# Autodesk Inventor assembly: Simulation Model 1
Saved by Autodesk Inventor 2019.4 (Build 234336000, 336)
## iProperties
Created: 2020-06
Part Number: Simulation Model 1
Document SubType Name: Assembly
Designer: Administrator
Title: Simulation Model 1
Author: Administrator
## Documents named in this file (9)
- c:\worker\convert-fusion-r04\tmp\job-1\85\output\files\12fc5e84-6763-4458-a53a-9d1ae2180744\7d9fe9d9-de22-4219-8f80-85885c66b3e3.iam
- c:\worker\convert-fusion-r04\tmp\job-1\85\output\files\12fc5e84-6763-4458-a53a-9d1ae2180744\Component1.ipt
- c:\worker\convert-fusion-r04\tmp\job-1\85\output\files\12fc5e84-6763-4458-a53a-9d1ae2180744\Motor v5.ipt
- c:\worker\convert-fusion-r04\tmp\job-1\85\output\files\12fc5e84-6763-4458-a53a-9d1ae2180744\Screw Assembled Reversed v5.iam
- c:\worker\convert-fusion-r04\tmp\job-1\85\output\files\12fc5e84-6763-4458-a53a-9d1ae2180744\Screw Assembled Reversed v5_1.iam
- c:\worker\convert-fusion-r04\tmp\job-1\85\output\files\12fc5e84-6763-4458-a53a-9d1ae2180744\Component1(Mirror) (2).ipt
- c:\worker\convert-fusion-r04\tmp\job-1\85\output\files\12fc5e84-6763-4458-a53a-9d1ae2180744\Component1(Mirror) (1).ipt
- c:\worker\convert-fusion-r04\tmp\job-1\85\output\files\12fc5e84-6763-4458-a53a-9d1ae2180744\Screw Mark 2 Assembled v7.iam
- c:\worker\convert-fusion-r04\tmp\job-1\85\output\files\12fc5e84-6763-4458-a53a-9d1ae2180744\Screw Mark 2 Assembled v7_1.iam
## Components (11 placed, 6 different names)
1. Component1:1
2. Motor v5:1
3. Motor v5:2
4. Motor v5:3
5. Motor v5:4
6. Screw Assembled Reversed v5:1 [sub-assembly]
7. Screw Assembled Reversed v5:2 [sub-assembly]
8. Component1(Mirror) (2):1
9. Component1(Mirror) (1):1
10. Screw Mark 2 Assembled v7:1 [sub-assembly]
11. Screw Mark 2 Assembled v7:2 [sub-assembly]
